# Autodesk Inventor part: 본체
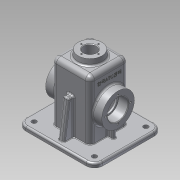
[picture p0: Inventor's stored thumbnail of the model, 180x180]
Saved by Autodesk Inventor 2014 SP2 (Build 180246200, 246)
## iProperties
Created: 2016-08
Part Number: 본체
Material: 알루미늄 6061
Document SubType Name: Modeling
Designer: user
Density: 2.71 g/cm^3
Appearance: 알루미늄 - 평지
Author: user
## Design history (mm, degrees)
sketch "스케치1"
  geometry: L1 (-32.5, -32.5)-(32.5, -32.5); L2 (32.5, -32.5)-(32.5, 32.5); L3 (32.5, 32.5)-(-32.5, 32.5); L4 (-32.5, 32.5)-(-32.5, -32.5); L5 (-32.5, -32.5)-(32.5, 32.5); L6 (32.5, -32.5)-(-32.5, 32.5); 1 further point
  constraints: 12 end point, 2 midpoint, 2 parallel, 1 horizontal, 1 perpendicular
  dimensions: "d0" = 65 distance of L3.end L2.end; "d1" = 65 distance of L2.end L1.end
extrude "돌출1" new body sketch "스케치1" distance "d2" = 110; taper "d3" = 0 deg
feature "쉘1" dims "d4" = 5
sketch "스케치2"
  geometry: L1 (65, -57.5)-(-65, -57.5); L2 (-65, -57.5)-(-65, 57.5); L3 (-65, 57.5)-(65, 57.5); L4 (65, 57.5)-(65, -57.5); L5 (65, -57.5)-(-65, 57.5); L6 (-65, -57.5)-(65, 57.5); L7 (-27.5, 27.5)-(-27.5, -27.5) reference; L8 (-27.5, -27.5)-(27.5, -27.5) reference; L9 (27.5, -27.5)-(27.5, 27.5) reference; L10 (27.5, 27.5)-(-27.5, 27.5) reference; L11 (-32.5, -32.5)-(32.5, -32.5) reference; L12 (-32.5, 32.5)-(-32.5, -32.5) reference; L13 (32.5, 32.5)-(-32.5, 32.5) reference; L14 (32.5, -32.5)-(32.5, 32.5) reference; 1 further point
  constraints: 12 end point, 2 midpoint, 2 parallel, 1 horizontal, 1 perpendicular
  dimensions: "d5" = 130 distance of L2.end L3.end; "d6" = 115 distance of L3.end L1.start
extrude "돌출2" join sketch "스케치2" distance "d7" = 10; taper "d8" = 0 deg
fillet "모깎기1" dims "d9" = 14
fillet "모깎기2" dims "d10" = 8
fillet "모깎기3" dims "d11" = 8
fillet "모깎기4" dims "d12" = 3
fillet "모깎기5" dims "d13" = 3
sketch "스케치3"
  geometry: L1 (51, 57.5)-(-51, 57.5) reference; L2 (-65, 43.5)-(-65, -43.5) reference; L3 (-51, -57.5)-(51, -57.5) reference; L4 (65, -43.5)-(65, 43.5) reference; L5 (60, -52.5)-(-60, -52.5); L6 (-60, -52.5)-(-60, 52.5); L7 (-60, 52.5)-(60, 52.5); L8 (60, 52.5)-(60, -52.5); L9 (60, -52.5)-(-60, 52.5); L10 (-60, -52.5)-(60, 52.5); A1 r 14 centre (51, 43.5) between (65, 43.5) and (51, 57.5) reference; A2 r 14 centre (-51, 43.5) between (-51, 57.5) and (-65, 43.5) reference; A3 r 14 centre (-51, -43.5) between (-65, -43.5) and (-51, -57.5) reference; A4 r 14 centre (51, -43.5) between (51, -57.5) and (65, -43.5) reference; 1 further point
  constraints: 12 end point, 2 midpoint, 2 parallel, 1 horizontal, 1 perpendicular
  dimensions: "d14" = 120 distance of L6.end L7.end; "d15" = 105 distance of L5.end L6.end
extrude "돌출3" cut sketch "스케치3" distance "d16" = 3; taper "d17" = 0 deg
fillet "모깎기6" dims "d18" = 9
sketch "스케치4"
  geometry: L1 (51, 43.5)-(-51, 43.5); L2 (-51, 43.5)-(-51, -43.5); L3 (-51, -43.5)-(51, -43.5); L4 (51, -43.5)-(51, 43.5); L5 (51, 43.5)-(-51, -43.5); L6 (-51, 43.5)-(51, -43.5); A1 r 9 centre (-51, -43.5) between (-60, -43.5) and (-51, -52.5) reference; 5 further points
  constraints: 12 end point, 4 coincident, 2 midpoint, 2 parallel, 1 horizontal, 1 perpendicular
  dimensions: "d19" = 102 distance of L3.end L2.end (derived); "d20" = 87 distance of L2.end L1.end (derived)
hole "구멍1" sketch "스케치4" at (51, -43.5), (-51, -43.5), (-51, 43.5), (51, 43.5) diameter "d21" = 8; stored, may be unused: countersink angle "d25" = 90 deg, drill point angle "d27" = 118 deg; dims "d22" = 6, "d23" = 4, "d24" = 2, "d26" = 8
fillet "모깎기7" dims "d28" = 3
node "작업 평면1"
sketch "스케치5"
  geometry: L1 (-10, -19)-(-10, 68) reference; C1 r 27.5 at (45, 24.5); 2 further points
  constraints: 1 centre point, 1 horizontal alignment, 1 midpoint
  dimensions: "d30" = 55 diameter of C1; "d31" = 55 distance of point (-10, 24.5) C1.centre
extrude "돌출4" join sketch "스케치5" stored distance "d32" = 3; taper "d33" = 0 deg
fillet "모깎기8" dims "d34" = 3
hole "구멍2" diameter "d37" = 30; stored, may be unused: countersink angle "d41" = 90 deg, drill point angle "d43" = 118 deg; dims "d35" = 10, "d36" = 10, "d38" = 6, "d39" = 35, "d40" = 17, "d42" = 8
sketch "스케치6"
  geometry: L1 (27.5, 102)-(27.5, 0) reference; L2 (51, 10)-(-51, 10) reference; L3 (42.5, 10)-(42.5, 27.5); L4 (47.5, 27.5)-(35.5, 27.5) reference; 1 further point
  constraints: 2 end point, 2 point on line, 1 perpendicular
  dimensions: "d44" = 15 distance between parallel lines of L1 L3
feature "리브1" sketch "스케치6" dims "d45" = 1, "d46" = 6, "d47" = 0, "d48" = 0, "d49" = 1, "d50" = 1
sketch "스케치7" dims "d51" = 42
  geometry: C1 r 17.5 at (0, 0) reference; C2 r 27.5 at (0, 0) reference; 3 further points
  constraints: 2 vertical alignment, 1 coincident, 2 other
hole "구멍3" sketch "스케치7" at (0, 21) diameter "d52" = 3.242; stored, may be unused: countersink angle "d56" = 90 deg, drill point angle "d58" = 118 deg; dims "d53" = 8, "d54" = 35, "d55" = 17, "d57" = 10
chamfer "모따기1" distance "d62" = 1; stored, may be unused: second distance "d63" = 2, angle "d64" = 45 deg
fillet "모깎기9" dims "d65" = 0.3
chamfer "모따기2" distance "d66" = 1; stored, may be unused: second distance "d67" = 2, angle "d68" = 45 deg
fillet "모깎기10" dims "d69" = 0.3
fillet "모깎기11" dims "d70" = 3
node "작업 평면2"
sketch "스케치8"
  geometry: C1 r 20 at (0, 0); 1 further point
  constraints: 1 centre point, 1 coincident
  dimensions: "d72" = 40 diameter of C1
extrude "돌출5" join sketch "스케치8" stored distance "d73" = 3; taper "d74" = 7 deg
fillet "모깎기12" dims "d75" = 3
hole "구멍4" diameter "d78" = 21; stored, may be unused: countersink angle "d82" = 90 deg, drill point angle "d84" = 118 deg; dims "d76" = 10, "d77" = 10, "d79" = 8, "d80" = 35, "d81" = 17, "d83" = 10
chamfer "모따기3" distance "d85" = 1; stored, may be unused: second distance "d86" = 2, angle "d87" = 45 deg
sketch "스케치9" dims "d88" = 29
  geometry: C1 r 11.5 at (0, 0) reference; 2 further points
  constraints: 2 vertical alignment, 1 coincident, 2 other
hole "구멍5" sketch "스케치9" at (0, 14.5) diameter "d89" = 2.459; stored, may be unused: countersink angle "d93" = 90 deg, drill point angle "d95" = 118 deg; dims "d90" = 7, "d91" = 35, "d92" = 17, "d94" = 9
sketch "스케치10"
  geometry: L1 (-57.5, 3)-(-57.5, 7) reference; L2 (-54.5, 10)-(-43.5, 10) reference; L3 (-32.5, 10)-(-32.5, 102) reference; L4 (-49.5, 10)-(-41.068, 70); L5 (-41.068, 70)-(-32.5, 70); L6 (-43.5, 0)-(-52.5, 0) reference; 1 further point
  constraints: 4 end point, 2 point on line, 1 perpendicular
  dimensions: "d99" = 8 distance from line of L4.start L1; "d100" = 8 deg angle of L1 L4; "d101" = 70 distance between parallel lines of L6 L5
feature "리브2" sketch "스케치10" dims "d102" = 1, "d103" = 10, "d104" = 0, "d105" = 0, "d106" = 1, "d107" = 1
fillet "모깎기13" dims "d108" = 3
fillet "모깎기14" dims "d109" = 3
fillet "모깎기15" dims "d110" = 3
fillet "모깎기16" dims "d111" = 3
fillet "모깎기17" dims "d112" = 3
fillet "모깎기18" dims "d113" = 3
fillet "모깎기19" dims "d114" = 1
sketch "스케치11"
  geometry: L1 (-18, 4.5)-(-18, 44.5) reference; L2 (0, -8)-(91, -8) reference; 2 further points
  constraints: 1 other
  dimensions: "d115" = 32.5 distance from line of point (8, 24.5) L2; "d116" = 26 distance from line of point (8, 24.5) L1
feature "엠보싱1" sketch "스케치11" dims "d117" = 0.5, "d118" = 0
node "솔리드1"
pattern_circular "원형 패턴1" dims angle "d60" = 360 deg
mirror "대칭1"
pattern_circular "원형 패턴2" dims angle "d97" = 360 deg
mirror "대칭2"
node "투영된 루프1"
other parameters: "d29" = 15
